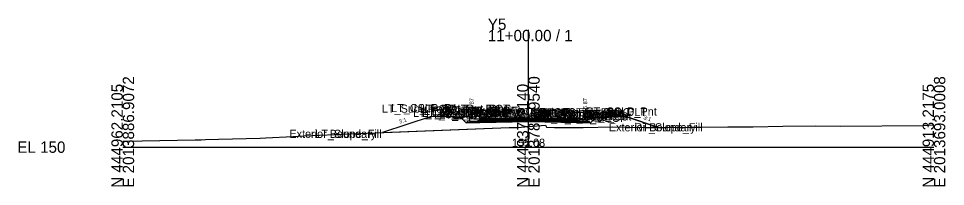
# Model space of a CAD drawing. Extents: x -26 to 203, y -10 to 4517.
# Drawn here: x -25.7 to 202.8, y 1990.3 to 2031.7 of the extents above; entities that cross this region are included whole.
import ezdxf

# ---------------------------------------------------------------- set-up
doc = ezdxf.new("R2010")
doc.units = 0
for name, color, linetype in [('Default', 7, 'Continuous'), ('Exist Cross Section Cell', 7, 'Continuous'), ('Exist XS Center Line Elevation Label', 7, 'Continuous'), ('Exist XS Ground Line', 7, 'Continuous'), ('Prop CMT Conc Surface', 7, 'Continuous'), ('Prop CMT Concrete Structures', 7, 'Continuous'), ('Prop CMT Pvmt Course 1', 7, 'Continuous'), ('Prop CMT Pvmt Course 1 CG', 7, 'Continuous'), ('Prop CMT Pvmt Course 2', 7, 'Continuous'), ('Prop CMT Pvmt Course 3', 7, 'Continuous'), ('Prop CMT Pvmt Surface', 7, 'Continuous'), ('Prop CMT Slope Grass', 7, 'Continuous'), ('Prop CMT Subgrade Earthwork', 7, 'Continuous'), ('Prop XS Earthwork Shape', 7, 'Continuous'), ('Prop XS Hydro Elevations', 7, 'Continuous'), ('Prop XS SE Text', 7, 'Continuous'), ('Prop XS Side Slope Text', 7, 'Continuous'), ('Scratch_Level_0', 7, 'Continuous')]:
    doc.layers.add(name, color=color, linetype=linetype)

msp = doc.modelspace()

# ---------------------------------------------------------------- linework, layer by layer
at = {"layer": 'Exist Cross Section Cell'}
for p, q in [((100, 2000), (100, 2028.9)), ((0, 2000), (100, 2000)), ((100, 2000), (200, 2000))]:
    msp.add_line(p, q, dxfattribs=at)
at = {"layer": 'Exist XS Ground Line'}
msp.add_lwpolyline([(0, 2001.49), (0.41, 2001.5), (17.86, 2001.8), (19.37, 2001.84), (20.37, 2001.89), (23.62, 2001.94), (33.88, 2002.19), (35.24, 2002.26), (41.92, 2002.62), (44.69, 2002.76), (56.14, 2003.25), (95.29, 2004.86), (97.36, 2004.86), (100, 2005.08), (104.21, 2005.43), (104.47, 2004.89), (106.41, 2004.87), (113.51, 2004.83), (120.85, 2004.97), (128.88, 2004.82), (134.32, 2004.87), (140.36, 2004.96), (142.5, 2004.96), (149.19, 2004.99), (155.4, 2004.99), (162.73, 2005.13), (170.82, 2005.24), (177, 2005.2), (197.46, 2005.34), (200, 2005.5)], dxfattribs=at)
at = {"layer": 'Prop CMT Conc Surface'}
for points in [[(86, 2006.87), (86, 2007.37), (85.5, 2007.37)], [(88, 2006.99), (86, 2006.87)], [(112, 2006.99), (114, 2006.87)], [(114, 2006.87), (114, 2007.37), (114.5, 2007.37)]]:
    msp.add_lwpolyline(points, dxfattribs=at)
at = {"layer": 'Prop CMT Concrete Structures'}
for points in [[(88, 2006.99), (86, 2006.87), (86, 2007.37), (85.5, 2007.37)], [(85.5, 2007.37), (85.5, 2006.36), (88, 2006.41)], [(88, 2006.41), (88, 2006.99)], [(112, 2006.99), (114, 2006.87), (114, 2007.37), (114.5, 2007.37)], [(114.5, 2007.37), (114.5, 2006.36), (112, 2006.41)], [(112, 2006.41), (112, 2006.99)]]:
    msp.add_lwpolyline(points, dxfattribs=at)
at = {"layer": 'Prop CMT Pvmt Course 1'}
for points in [[(100, 2007.23), (88, 2006.99)], [(88, 2006.99), (88, 2006.74)], [(88, 2006.74), (100, 2006.98)], [(100, 2006.98), (100, 2007.23)], [(100, 2007.23), (112, 2006.99)], [(100, 2006.98), (100, 2007.23)], [(112, 2006.74), (100, 2006.98)], [(112, 2006.99), (112, 2006.74)]]:
    msp.add_lwpolyline(points, dxfattribs=at)
msp.add_lwpolyline([(100, 2006.98), (100, 2007.11), (100, 2007.11), (100, 2006.98)], close=True, dxfattribs=at)
msp.add_lwpolyline([(100, 2006.98), (100, 2007.11), (100, 2007.11), (100, 2006.98)], close=True, dxfattribs=at)
at = {"layer": 'Prop CMT Pvmt Course 1 CG'}
for points in [[(88, 2006.41), (85, 2006.35), (84.66, 2006.01)], [(84.66, 2006.01), (88, 2006.08)], [(88, 2006.08), (88, 2006.41)], [(112, 2006.41), (115, 2006.35), (115.34, 2006.01)], [(112, 2006.08), (112, 2006.41)], [(115.34, 2006.01), (112, 2006.08)]]:
    msp.add_lwpolyline(points, dxfattribs=at)
at = {"layer": 'Prop CMT Pvmt Course 2'}
for points in [[(100, 2006.98), (88, 2006.74)], [(88, 2006.74), (88, 2006.41)], [(88, 2006.41), (100, 2006.65)], [(100, 2006.65), (100, 2006.98)], [(100, 2006.65), (100, 2006.98)], [(100, 2006.98), (112, 2006.74)], [(112, 2006.41), (100, 2006.65)], [(112, 2006.74), (112, 2006.41)]]:
    msp.add_lwpolyline(points, dxfattribs=at)
at = {"layer": 'Prop CMT Pvmt Course 3'}
for points in [[(100, 2006.65), (88, 2006.41)], [(100, 2006.32), (100, 2006.65)], [(100, 2006.65), (112, 2006.41)], [(100, 2006.32), (100, 2006.65)], [(88, 2006.41), (88, 2006.08)], [(88, 2006.08), (100, 2006.32)], [(112, 2006.08), (100, 2006.32)], [(112, 2006.41), (112, 2006.08)]]:
    msp.add_lwpolyline(points, dxfattribs=at)
at = {"layer": 'Prop CMT Pvmt Surface'}
for points in [[(100, 2007.23), (88, 2006.99)], [(100, 2007.23), (112, 2006.99)]]:
    msp.add_lwpolyline(points, dxfattribs=at)
at = {"layer": 'Prop CMT Slope Grass'}
for points in [[(85.5, 2007.37), (76, 2007.56), (64.03, 2003.57)], [(114.5, 2007.37), (124, 2007.56), (132.13, 2004.85)]]:
    msp.add_lwpolyline(points, dxfattribs=at)
at = {"layer": 'Prop CMT Subgrade Earthwork'}
for points in [[(88, 2006.08), (84.66, 2006.01), (83.25, 2007.42)], [(112, 2006.08), (115.34, 2006.01), (116.75, 2007.42)], [(100, 2006.32), (88, 2006.08)], [(100, 2006.32), (112, 2006.08)]]:
    msp.add_lwpolyline(points, dxfattribs=at)
at = {"layer": 'Prop XS Earthwork Shape'}
msp.add_lwpolyline([(128.88, 2004.82), (132.13, 2004.85), (124, 2007.56), (116.75, 2007.42), (115.34, 2006.01), (112, 2006.08), (100, 2006.32), (88, 2006.08), (84.66, 2006.01), (83.25, 2007.42), (76, 2007.56), (64.03, 2003.57), (95.29, 2004.86), (97.36, 2004.86), (100, 2005.08), (104.21, 2005.43), (104.47, 2004.89), (106.41, 2004.87), (113.51, 2004.83), (120.85, 2004.97)], close=True, dxfattribs=at)

# ---------------------------------------------------------------- texts
at = {"layer": 'Default'}
msp.add_text('-', height=0.0001, dxfattribs=at).set_placement((0, 2000))
at = {"layer": 'Exist Cross Section Cell'}
for s, p in [('Y5', (90, 2028.9)), ('11+00.00 / 1', (90, 2026.1)), ('EL 150', (-26, 1998.6))]:
    msp.add_text(s, height=2.8, dxfattribs=at).set_placement(p)
for s, p in [('E 2013886.9072', (2.8, 1990)), ('E 2013789.9540', (102.8, 1990)), ('E 2013693.0008', (202.8, 1990)), ('N 444962.2105', (0, 1990)), ('N 444937.7140', (100, 1990)), ('N 444913.2175', (200, 1990))]:
    msp.add_text(s, height=2.8, rotation=90, dxfattribs=at).set_placement(p)
at = {"layer": 'Exist XS Center Line Elevation Label'}
msp.add_text('155.08', height=2, dxfattribs=at).set_placement((95.96, 2000.08))
at = {"layer": 'Prop XS Hydro Elevations'}
for p in [(86.5, 2007.85), (114.5, 2007.85)]:
    msp.add_text('156.87', height=1, rotation=90, dxfattribs=at).set_placement(p)
at = {"layer": 'Prop XS SE Text'}
for rotation, p in [(1.1458, (92.35, 2008)), (358.8542, (104.29, 2008.09))]:
    msp.add_text('0.020', height=1, rotation=rotation, dxfattribs=at).set_placement(p)
at = {"layer": 'Prop XS Side Slope Text'}
for rotation, p in [(18.4332, (68.29, 2005.77)), (341.5667, (128.3, 2006.94))]:
    msp.add_text('3:1', height=1, rotation=rotation, dxfattribs=at).set_placement(p)
at = {"layer": 'Scratch_Level_0'}
for s, p in [('LT_Sub_Trench_Out_DLT', (63.9, 2008.49)), ('LT_CSLP_Pnt', (66.17, 2008.63)), ('LT_CG1_Shelf_Out', (71.55, 2007.47)), ('LT_CG_Top_Face', (73.26, 2008.44)), ('LT_CG_Top_BOC', (73.78, 2008.44)), ('LT_CG_Bot_BOC', (73.81, 2007.46)), ('LT_CG_Top_Gut', (74.24, 2007.94)), ('LT_Sub_OEOP', (74.79, 2007.15)), ('LT_CG_Bot_IE', (77.91, 2007.38)), ('LT_Sub_OEOT', (78.08, 2007.05)), ('LT_PV2_OEOT', (78.17, 2007.71)), ('LT_PV3_OEOT', (78.17, 2007.38)), ('LT_PV1_OEOT', (78.74, 2007.96)), ('RT_PV2_OEEOP', (89.26, 2007.35)), ('RT_PV3_OEEOP', (89.26, 2007.02)), ('LT_PV2_OEEOP', (89.31, 2007.35)), ('LT_PV3_OEEOP', (89.31, 2007.02)), ('RT_PV1_OEEOP', (89.83, 2007.48)), ('LT_PV1_OEEOP', (89.87, 2007.48)), ('RT_PV2_IEEOP', (89.91, 2007.35)), ('LT_PV2_IEEOP', (89.95, 2007.35)), ('RT_PV1_IEEOP', (90.47, 2007.48)), ('LT_PV1_IEEOP', (90.52, 2007.48)), ('PV2_PGL', (93.91, 2007.35)), ('PV1_PGL', (94.47, 2007.6)), ('RT_Sub_Trench_Out_DLT', (97.29, 2007.65)), ('RT_CG_Top_Face', (101.21, 2007.6)), ('RT_PV2_OEOT', (102.13, 2006.99)), ('RT_CG_Top_Gut', (102.19, 2007.1)), ('RT_PV1_OEOT', (102.69, 2007.24)), ('RT_CG_Top_BOC', (102.74, 2007.6)), ('RT_CSLP_Pnt', (114.13, 2007.79)), ('RT_Sub_OEEOP', (89.17, 2006.69)), ('LT_Sub_OEEOP', (89.21, 2006.69)), ('RT_CG1_Shelf_Out', (101.5, 2006.57)), ('RT_CG_Bot_IE', (101.87, 2006.66)), ('RT_Sub_OEOT', (102.03, 2006.33)), ('RT_PV3_OEOT', (102.13, 2006.66)), ('RT_CG_Bot_BOC', (102.77, 2006.59)), ('RT_Sub_OEOP', (105.41, 2006.23)), ('Exterior Boundary', (41.08, 2002.28)), ('LT_Slope_Fill', (47.46, 2002.28)), ('Exterior Boundary', (119.84, 2003.89)), ('RT_Slope_Fill', (126.17, 2003.89))]:
    msp.add_text(s, height=2, dxfattribs=at).set_placement(p)

doc.saveas('drawing.dxf')
